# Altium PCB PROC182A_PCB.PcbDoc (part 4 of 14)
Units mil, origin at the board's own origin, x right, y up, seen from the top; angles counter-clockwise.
Board outline 3168.31 x 3700.79 mil, 8 copper layers (Top Layer, L2_GND1, L3_SIG1, L4_PWR1, L5_PWR2, L6_SIG2, L7_GND2, Bottom Layer), stack 58.1 mil thick; 580 components, 391 nets, 8314 pads, 4370 vias.
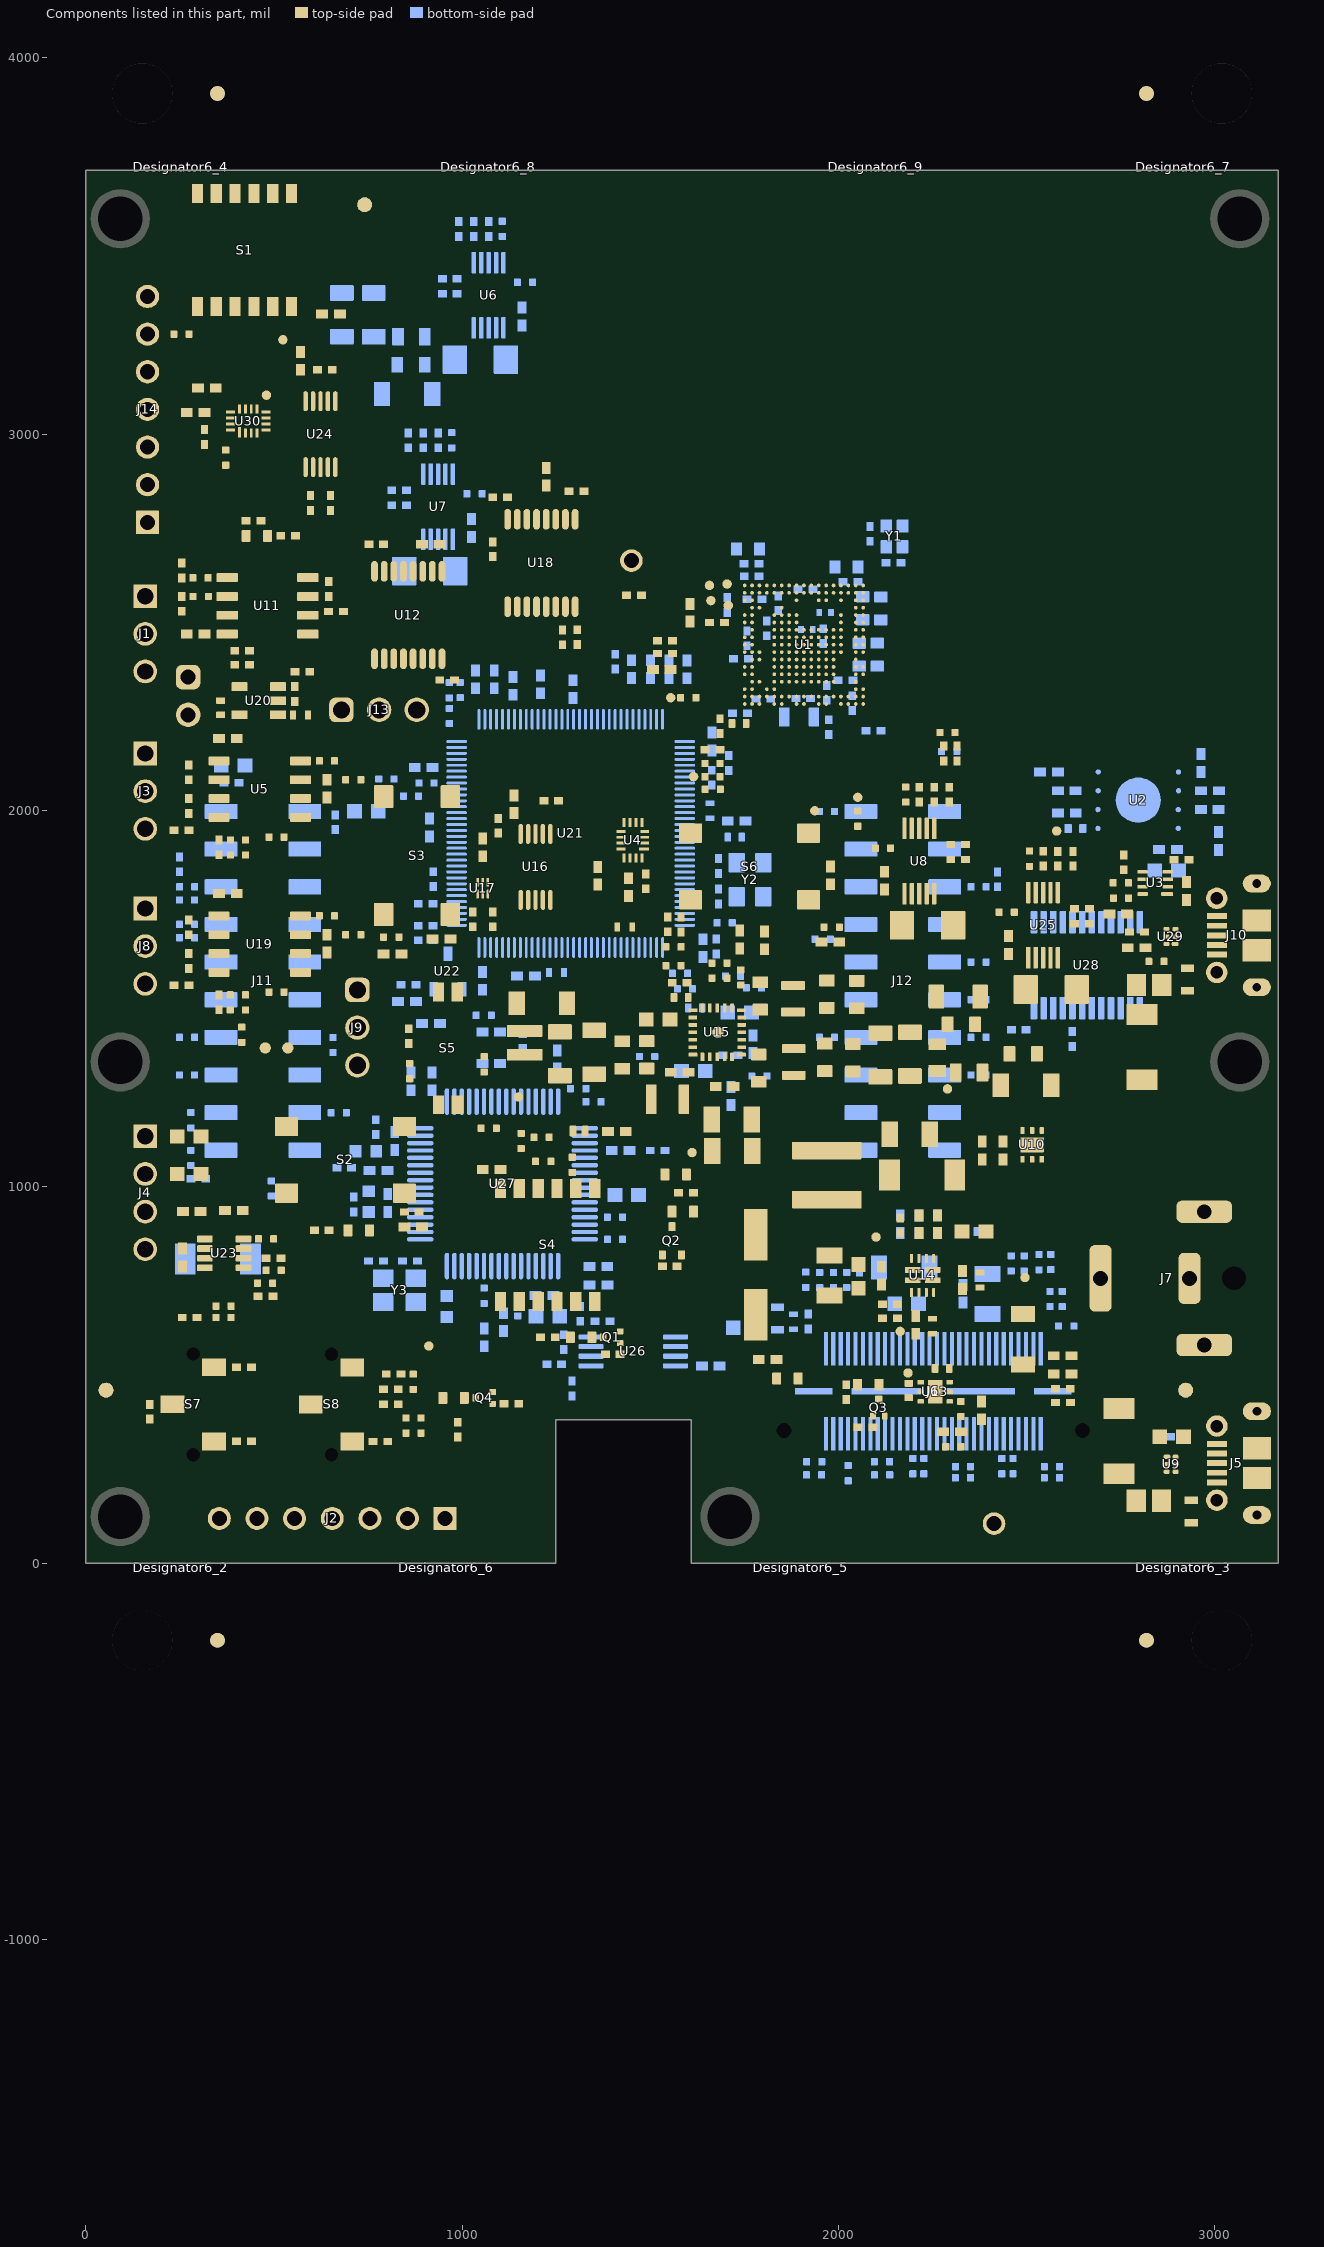
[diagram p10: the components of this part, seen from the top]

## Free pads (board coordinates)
  round 1 on Mech13: 0(1166.41,3201.26)
  round 10 on Mech16: 1(51.93,-1645.55) 1(51.93,-1645.55) 1(51.93,3654.45) 1(51.93,3654.45) 1(498.84,933.96) 1(512.82,933.96) 1(1827.42,1591.75) 1(1838.84,1591.75) 1(2281.51,930.17) 1(2297.85,930.17) 1(2467.76,1576.45) 1(2479.77,1576.45) 1(2612.3,1685.9) 1(2612.3,2360.9) 1(2622.49,1685.9) 1(2622.49,2360.9) 1(2807.83,-1645.55) 1(2807.83,-1645.55) 1(2807.83,3654.45) 1(2807.83,3654.45) 1(2808,1436.99) 1(2808,1830.69) 1(2808,2111.99) 1(2808,2505.69)
  round 7.87 on Mech16: 1(88.55,490.85) 1(89.2,516.08) 1(91.65,3514.31) 1(92.3,3539.55) 1(104.28,447.28) 1(105.05,555.83) 1(107.38,3470.75) 1(108.15,3579.3) 1(116.37,432.53) 1(119.47,3455.99) 1(121.82,574.49) 1(124.92,3597.95) 1(154.21,409.14) 1(154.21,592.82) 1(157.31,3432.61) 1(157.31,3616.29) 1(170.47,596.72) 1(173.57,3620.19) 1(179.46,404.32) 1(182.56,3427.79) 1(209.47,594.61) 1(212.56,3618.07) 1(222.4,411.76) 1(224.15,589.45) 1(225.5,3435.22) 1(227.25,3612.92) 1(239.67,421.21) 1(242.77,3444.67) 1(255.77,566.86) 1(258.87,3590.32) 1(265.38,447.28) 1(268.48,3470.75) 1(268.67,549.39) 1(271.77,3572.85) 1(274.05,463.41) 1(277.15,3486.88) 1(280.45,516.08) 1(281.52,496.15) 1(283.55,3539.55) 1(284.62,3519.61) 1(348.27,462.43) 1(348.27,501.8) 1(370.78,1047.45) 1(370.78,1047.45) 1(370.78,1061.62) 1(370.78,2033.28) 1(370.78,2047.45) 1(370.78,2047.45) 1(378.99,647.44) 1(378.99,761.62) 1(378.99,833.28) 1(378.99,947.46) 1(378.99,947.46) 1(379.54,647.45) 1(423.07,446.68) 1(423.07,501.8) 1(478.99,936.43) 1(478.99,936.43) 1(478.99,947.46) 1(478.99,947.46) 1(478.99,947.46) 1(479.54,647.45) 1(479.54,647.45) 1(479.54,661.62) 1(519.1,936.43) 1(519.1,936.43) 1(519.1,947.46) 1(519.1,947.46) 1(521.97,553.8) 1(521.97,561.67) 1(521.97,452.42) 1(521.97,472.1) 1(570.78,1047.45) 1(570.78,1047.45) 1(570.78,1061.62) 1(570.78,2033.28) 1(570.78,2047.45) 1(570.78,2047.45) 1(606.62,457.34) 1(606.62,465.21) 1(606.62,553.8) 1(606.62,561.67) 1(634.39,639.07) 1(634.39,723.72) 1(641.39,789.13) 1(641.39,873.77) 1(642.27,639.07) 1(642.27,723.72) 1(649.27,789.13) 1(649.27,873.77) 1(673.7,1905.54) 1(673.7,1905.54) 1(673.7,2035.47) 1(673.7,2035.47) 1(718.13,313.18) 1(718.13,397.83) 1(722.13,494.18) 1(722.13,578.83) 1(723.96,639.07) 1(726.01,313.18) 1(726.01,397.83) 1(730.01,494.18) 1(730.01,578.83) 1(730.85,723.72) 1(730.96,789.13) 1(737.85,873.77) 1(738.72,723.72) 1(743.64,639.07) 1(745.72,873.77) 1(750.64,789.13) 1(760.31,1905.54) 1(760.31,2035.47) 1(807.7,313.18) 1(811.7,494.18) 1(814.59,397.83) 1(818.59,578.83) 1(822.46,397.83) 1(826.46,578.83) 1(827.38,313.18) 1(831.38,494.18) 1(835.9,1474.32) 1(835.9,1494.01) 1(835.9,1494.01) 1(855.27,1151.84) 1(855.27,1194.16) 1(856.28,1905.54) 1(856.28,2035.47) 1(867.39,1494.01) 1(922.51,1494.01) 1(942.9,1905.54) 1(942.9,1905.54) 1(942.9,2035.47) 1(942.9,2035.47) 1(954.01,1474.32) 1(954.01,1494.01) 1(954.01,1494.01) 1(975.34,1111.48) 1(975.34,1194.16) 1(989.84,321.77) 1(994.76,237.13) 1(1002.64,237.13) 1(1009.53,321.77) 1(1091.22,237.13) 1(1091.22,321.77) 1(1099.09,237.13) 1(1099.09,321.77) 1(1126.49,1380.34) 1(1126.49,1396.09) 1(1126.49,1411.84) 1(1126.49,1427.58) 1(1126.49,1443.33) 1(1126.49,1459.08) 1(1126.49,1474.83) 1(1126.49,1490.58) 1(1126.49,1506.32) 1(1126.49,1522.07) 1(1126.49,1537.82) 1(1126.49,1553.57) 1(1126.49,1569.32) 1(1126.49,1585.06) 1(1126.49,1600.81) 1(1126.49,1616.56) 1(1126.49,1632.31) 1(1126.49,1648.06) 1(1126.49,1663.8) 1(1126.49,1679.55) 1(1126.49,1695.3) 1(1126.49,1711.05) 1(1126.49,1726.8) 1(1126.49,1742.54) 1(1126.49,1758.29) 1(1126.49,1774.04) 1(1126.49,1789.79) 1(1126.49,1805.54) 1(1126.49,1821.28) 1(1126.49,1837.03) 1(1126.49,1852.78) 1(1126.49,1868.53) 1(1173.74,1380.34) 1(1173.74,1396.09) 1(1173.74,1411.84) 1(1173.74,1427.58) 1(1173.74,1443.33) 1(1173.74,1459.08) 1(1173.74,1474.83) 1(1173.74,1490.58) 1(1173.74,1506.32) 1(1173.74,1522.07) 1(1173.74,1537.82) 1(1173.74,1553.57) 1(1173.74,1569.32) 1(1173.74,1585.06) 1(1173.74,1600.81) 1(1173.74,1616.56) 1(1173.74,1632.31) 1(1173.74,1648.06) 1(1173.74,1663.8) 1(1173.74,1679.55) 1(1173.74,1695.3) 1(1173.74,1711.05) 1(1173.74,1726.8) 1(1173.74,1742.54) 1(1173.74,1758.29) 1(1173.74,1774.04) 1(1173.74,1789.79) 1(1173.74,1805.54) 1(1173.74,1821.28) 1(1173.74,1837.03) 1(1173.74,1852.78) 1(1173.74,1868.53) 1(1205.23,1376.4) 1(1205.23,1376.4) 1(1205.23,1872.47) 1(1205.23,1872.47) 1(1209.17,1297.66) 1(1209.17,1344.91) 1(1209.17,1903.96) 1(1209.17,1951.21) 1(1224.92,1297.66) 1(1224.92,1344.91) 1(1224.92,1903.96) 1(1224.92,1951.21) 1(1240.66,1297.66) 1(1240.66,1344.91) 1(1240.66,1903.96) 1(1240.66,1951.21) 1(1256.41,1297.66) 1(1256.41,1344.91) 1(1256.41,1903.96) 1(1256.41,1951.21) 1(1272.16,1297.66) 1(1272.16,1344.91) 1(1272.16,1903.96) 1(1272.16,1951.21) 1(1287.91,1297.66) 1(1287.91,1344.91) 1(1287.91,1903.96) 1(1287.91,1951.21) 1(1303.66,1297.66) 1(1303.66,1344.91) 1(1303.66,1903.96) 1(1303.66,1951.21) 1(1319.4,1297.66) 1(1319.4,1344.91) 1(1319.4,1903.96) 1(1319.4,1951.21) 1(1335.15,1297.66) 1(1335.15,1344.91) 1(1335.15,1903.96) 1(1335.15,1951.21) 1(1348.35,237.58) 1(1348.35,245.46) 1(1348.35,334.04) 1(1348.35,341.91) 1(1350.9,1297.66) 1(1350.9,1344.91) 1(1350.9,1903.96) 1(1350.9,1951.21) 1(1366.65,1297.66) 1(1366.65,1344.91) 1(1366.65,1903.96) 1(1366.65,1951.21) 1(1382.4,1297.66) 1(1382.4,1344.91) 1(1382.4,1903.96) 1(1382.4,1951.21) 1(1398.14,1297.66) 1(1398.14,1344.91) 1(1398.14,1903.96) 1(1398.14,1951.21) 1(1413.89,1297.66) 1(1413.89,1344.91) 1(1413.89,1903.96) 1(1413.89,1951.21) 1(1429.64,1297.66) 1(1429.64,1344.91) 1(1429.64,1903.96) 1(1429.64,1951.21) 1(1433,327.15) 1(1433,346.84) 1(1433,237.58) 1(1433,245.46) 1(1445.39,1297.66) 1(1445.39,1344.91) 1(1445.39,1903.96) 1(1445.39,1951.21) 1(1461.14,1297.66) 1(1461.14,1344.91) 1(1461.14,1903.96) 1(1461.14,1951.21) 1(1476.89,1297.66) 1(1476.89,1344.91) 1(1476.89,1903.96) 1(1476.89,1951.21) 1(1492.63,1297.66) 1(1492.63,1344.91) 1(1492.63,1903.96) 1(1492.63,1951.21) 1(1508.38,1297.66) 1(1508.38,1344.91) 1(1508.38,1903.96) 1(1508.38,1951.21) 1(1524.13,1297.66) 1(1524.13,1344.91) 1(1524.13,1903.96) 1(1524.13,1951.21) 1(1539.88,1297.66) 1(1539.88,1344.91) 1(1539.88,1903.96) 1(1539.88,1951.21) 1(1555.63,1297.66) 1(1555.63,1344.91) 1(1555.63,1903.96) 1(1555.63,1951.21) 1(1571.37,1297.66) 1(1571.37,1344.91) 1(1571.37,1903.96) 1(1571.37,1951.21) 1(1587.12,1297.66) 1(1587.12,1344.91) 1(1587.12,1903.96) 1(1587.12,1951.21) 1(1602.87,1297.66) 1(1602.87,1344.91) 1(1602.87,1903.96) 1(1602.87,1951.21) 1(1618.62,1297.66) 1(1618.62,1344.91) 1(1618.62,1903.96) 1(1618.62,1951.21) 1(1634.37,1297.66) 1(1634.37,1344.91) 1(1634.37,1903.96) 1(1634.37,1951.21) 1(1650.11,1297.66) 1(1650.11,1344.91) 1(1650.11,1903.96) 1(1650.11,1951.21) 1(1665.86,1297.66) 1(1665.86,1344.91) 1(1665.86,1903.96) 1(1665.86,1951.21) 1(1681.61,1297.66) 1(1681.61,1344.91) 1(1681.61,1903.96) 1(1681.61,1951.21) 1(1697.36,1297.66) 1(1697.36,1344.91) 1(1697.36,1903.96) 1(1697.36,1951.21) 1(1701.29,1376.4) 1(1701.29,1376.4) 1(1701.29,1872.47) 1(1701.29,1872.47) 1(1716.69,905.12) 1(1732.58,1062.84) 1(1732.58,1062.84) 1(1732.58,1184.89) 1(1732.58,1184.89) 1(1732.79,1380.34) 1(1732.79,1396.09) 1(1732.79,1411.84) 1(1732.79,1427.58) 1(1732.79,1443.33) 1(1732.79,1459.08) 1(1732.79,1474.83) 1(1732.79,1490.58) 1(1732.79,1506.32) 1(1732.79,1522.07) 1(1732.79,1537.82) 1(1732.79,1553.57) 1(1732.79,1569.32) 1(1732.79,1585.06) 1(1732.79,1600.81) 1(1732.79,1616.56) 1(1732.79,1632.31) 1(1732.79,1648.06) 1(1732.79,1663.8) 1(1732.79,1679.55) 1(1732.79,1695.3) 1(1732.79,1711.05) 1(1732.79,1726.8) 1(1732.79,1742.54) 1(1732.79,1758.29) 1(1732.79,1774.04) 1(1732.79,1789.79) 1(1732.79,1805.54) 1(1732.79,1821.28) 1(1732.79,1837.03) 1(1732.79,1852.78) 1(1732.79,1868.53) 1(1775,-231.11) 1(1780.03,1380.34) 1(1780.03,1396.09) 1(1780.03,1411.84) 1(1780.03,1427.58) 1(1780.03,1443.33) 1(1780.03,1459.08) 1(1780.03,1474.83) 1(1780.03,1490.58) 1(1780.03,1506.32) 1(1780.03,1522.07) 1(1780.03,1537.82) 1(1780.03,1553.57) 1(1780.03,1569.32) 1(1780.03,1585.06) 1(1780.03,1600.81) 1(1780.03,1616.56) 1(1780.03,1632.31) 1(1780.03,1648.06) 1(1780.03,1663.8) 1(1780.03,1679.55) 1(1780.03,1695.3) 1(1780.03,1711.05) 1(1780.03,1726.8) 1(1780.03,1742.54) 1(1780.03,1758.29) 1(1780.03,1774.04) 1(1780.03,1789.79) 1(1780.03,1805.54) 1(1780.03,1821.28) 1(1780.03,1837.03) 1(1780.03,1852.78) 1(1780.03,1868.53) 1(1785.59,1027.17) 1(1815.12,278.25) 1(1815.12,278.25) 1(1815.12,306.79) 1(1815.12,481) 1(1815.12,490.84) 1(1815.12,490.84) 1(1824.96,490.84) 1(1843.67,278.25) 1(1843.89,-109.06) 1(1856.45,905.12) 1(1856.45,1027.17) 1(1858.57,1062.84) 1(1858.57,1062.84) 1(1858.57,1184.89) 1(1858.57,1184.89) 1(1872.3,1806) 1(1872.3,1806) 1(1872.3,1883.5) 1(1872.3,1883.5) 1(1872.3,1903.5) 1(1872.3,1903.5) 1(1872.3,1983.5) 1(1872.3,1983.5) 1(1872.3,2003.5) 1(1872.3,2003.5) 1(1872.3,2081) 1(1872.3,2081) 1(1881.8,1793.5) 1(1881.8,1793.5) 1(1881.8,2093.5) 1(1881.8,2093.5) 1(1882.3,1893.5) 1(1882.3,1893.5) 1(1882.3,1993.5) 1(1882.3,1993.5) 1(1885.3,1793.5) 1(1885.3,2093.5) 1(1885.3,2093.5) 1(1914.76,-231.11) 1(1914.76,-109.06) 1(1957.3,1793.5) 1(1957.3,2093.5) 1(1957.3,2093.5) 1(1960.3,1893.5) 1(1960.3,1893.5) 1(1960.3,1993.5) 1(1960.3,1993.5) 1(1960.8,1793.5) 1(1960.8,1793.5) 1(1960.8,2093.5) 1(1960.8,2093.5) 1(1970.3,1806) 1(1970.3,1806) 1(1970.3,1883.5) 1(1970.3,1883.5) 1(1970.3,1903.5) 1(1970.3,1903.5) 1(1970.3,1983.5) 1(1970.3,1983.5) 1(1970.3,2003.5) 1(1970.3,2003.5) 1(1970.3,2081) 1(1970.3,2081) 1(1998.19,278.25) 1(1998.19,490.84) 1(2008.04,278.25) 1(2008.04,278.25) 1(2008.04,288.09) 1(2008.04,481) 1(2008.04,490.84) 1(2008.04,490.84) 1(2070.78,1047.45) 1(2070.78,1047.45) 1(2070.78,1061.62) 1(2070.78,2033.28) 1(2070.78,2047.45) 1(2070.78,2047.45) 1(2161.47,647.44) 1(2161.47,761.62) 1(2161.47,833.28) 1(2161.47,947.46) 1(2161.47,947.46) 1(2162.02,647.45) 1(2246.76,317.85) 1(2246.76,325.73) 1(2246.76,216.48) 1(2246.76,236.16) 1(2261.47,936.43) 1(2261.47,936.43) 1(2261.47,947.46) 1(2261.47,947.46) 1(2261.47,947.46) 1(2262.02,647.45) 1(2262.02,647.45) 1(2262.02,661.62) 1(2270.78,1047.45) 1(2270.78,1047.45) 1(2270.78,1061.62) 1(2270.78,2033.28) 1(2270.78,2047.45) 1(2270.78,2047.45) 1(2301.58,936.43) 1(2301.58,936.43) 1(2301.58,947.46) 1(2301.58,947.46) 1(2303.86,-14.52) 1(2303.86,107.53) 1(2309.97,-1229.15) 1(2309.97,-1229.15) 1(2309.97,-1142.54) 1(2309.97,-1046.57) 1(2309.97,-959.95) 1(2309.97,-959.95) 1(2320.65,3534.31) 1(2321.3,3559.55) 1(2328.55,490.85) 1(2329.2,516.08) 1(2331.41,221.4) 1(2331.41,229.27) 1(2331.41,317.85) 1(2331.41,325.73) 1(2336.38,3490.75) 1(2337.15,3599.3) 1(2344.28,447.28) 1(2345.05,555.83) 1(2348.47,3475.99) 1(2353.92,3617.95) 1(2356.37,432.53) 1(2361.82,574.49) 1(2374.73,-14.52) 1(2385.3,1191) 1(2385.3,1191) 1(2385.3,1268.5) 1(2385.3,1268.5) 1(2385.3,1288.5) 1(2385.3,1288.5) 1(2385.3,1368.5) 1(2385.3,1368.5) 1(2385.3,1388.5) 1(2385.3,1388.5) 1(2385.3,1466) 1(2385.3,1466) 1(2386.31,3452.61) 1(2386.31,3636.29) 1(2394.21,409.14) 1(2394.21,592.82) 1(2394.8,1178.5) 1(2394.8,1178.5) 1(2394.8,1478.5) 1(2394.8,1478.5) 1(2395.3,1278.5) 1(2395.3,1278.5) 1(2395.3,1378.5) 1(2395.3,1378.5) 1(2398.3,1178.5) 1(2398.3,1178.5) 1(2398.3,1478.5) 1(2402.57,3640.19) 1(2410.47,596.72) 1(2411.56,3447.79) 1(2419.46,404.32) 1(2439.89,-1229.15) 1(2439.89,-1229.15) 1(2439.89,-1142.54) 1(2439.89,-1046.57) 1(2439.89,-959.95) 1(2439.89,-959.95) 1(2441.56,3638.07) 1(2443.63,107.53) 1(2449.47,594.61) 1(2454.5,3455.22) 1(2456.25,3632.92) 1(2462.4,411.76) 1(2464.15,589.45) 1(2470.3,1178.5) 1(2470.3,1178.5) 1(2470.3,1478.5) 1(2471.77,3464.67) 1(2473.3,1278.5) 1(2473.3,1278.5) 1(2473.3,1378.5) 1(2473.3,1378.5) 1(2473.8,1178.5) 1(2473.8,1178.5) 1(2473.8,1478.5) 1(2473.8,1478.5) 1(2474.24,1604.98) 1(2479.67,421.21) 1(2483.3,1191) 1(2483.3,1191) 1(2483.3,1268.5) 1(2483.3,1268.5) 1(2483.3,1288.5) 1(2483.3,1288.5) 1(2483.3,1368.5) 1(2483.3,1368.5) 1(2483.3,1388.5) 1(2483.3,1388.5) 1(2483.3,1466) 1(2483.3,1466) 1(2486.05,1671.91) 1(2487.87,3610.32) 1(2495.77,566.86) 1(2497.48,3490.75) 1(2500.77,3592.85) 1(2501.8,1604.98) 1(2501.8,1671.91) 1(2505.38,447.28) 1(2506.15,3506.88) 1(2508.67,549.39) 1(2512.55,3559.55) 1(2513.62,3539.61) 1(2514.05,463.41) 1(2520.45,516.08) 1(2521.52,496.15)
  round 7 on Mech16: 1(146.93,-380.05) 1(146.93,-380.05) 1(146.93,-339.05) 1(146.93,-339.05) 1(147.5,-330.06) 1(147.5,-330.06) 1(147.5,-289.06) 1(147.5,-289.06) 1(147.5,-231.63) 1(147.5,-231.63) 1(147.5,-190.63) 1(147.5,-190.63) 1(147.55,-281.52) 1(147.55,-281.52) 1(147.55,-240.52) 1(147.55,-240.52) 1(148.55,-432.52) 1(148.55,-432.52) 1(148.55,-391.52) 1(148.55,-391.52) 1(163.93,1511.95) 1(163.93,1511.95) 1(163.93,1552.95) 1(163.93,1552.95) 1(163.93,1560.95) 1(163.93,1560.95) 1(163.93,1601.95) 1(163.93,1601.95) 1(163.93,1462.95) 1(163.93,1462.95) 1(163.93,1503.95) 1(163.93,1503.95) 1(169.93,-380.05) 1(169.93,-339.05) 1(170.5,-330.06) 1(170.5,-289.06) 1(170.5,-231.63) 1(170.5,-190.63) 1(170.55,-281.52) 1(170.55,-240.52) 1(171.55,-432.52) 1(171.55,-391.52) 1(186.93,1511.95) 1(186.93,1552.95) 1(186.93,1560.95) 1(186.93,1601.95) 1(186.93,1462.95) 1(186.93,1503.95) 1(219.93,-380.05) 1(219.93,-339.05) 1(220.5,-330.06) 1(220.5,-289.06) 1(220.5,-231.63) 1(220.5,-190.63) 1(220.55,-281.52) 1(220.55,-240.52) 1(221.55,-432.52) 1(221.55,-391.52) 1(236.93,1511.95) 1(236.93,1552.95) 1(236.93,1560.95) 1(236.93,1601.95) 1(236.93,1462.95) 1(236.93,1503.95) 1(242.93,-380.05) 1(242.93,-380.05) 1(242.93,-339.05) 1(242.93,-339.05) 1(243.5,-330.06) 1(243.5,-330.06) 1(243.5,-289.06) 1(243.5,-289.06) 1(243.5,-231.63) 1(243.5,-231.63) 1(243.5,-190.63) 1(243.5,-190.63) 1(243.55,-281.52) 1(243.55,-281.52) 1(243.55,-240.52) 1(243.55,-240.52) 1(244.55,-432.52) 1(244.55,-432.52) 1(244.55,-391.52) 1(244.55,-391.52) 1(259.93,1511.95) 1(259.93,1511.95) 1(259.93,1552.95) 1(259.93,1552.95) 1(259.93,1560.95) 1(259.93,1560.95) 1(259.93,1601.95) 1(259.93,1601.95) 1(259.93,1462.95) 1(259.93,1462.95) 1(259.93,1503.95) 1(259.93,1503.95) 1(365.55,-403.52) 1(365.55,-403.52) 1(365.55,-362.52) 1(365.55,-362.52) 1(366.55,-76.52) 1(366.55,-76.52) 1(366.55,-35.52) 1(366.55,-35.52) 1(366.55,-25.52) 1(366.55,-25.52) 1(366.55,15.48) 1(366.55,15.48) 1(367.05,-353.02) 1(367.05,-353.02) 1(367.05,-330.02) 1(367.05,-280.02) 1(367.05,-257.02) 1(367.05,-257.02) 1(367.55,76.48) 1(367.55,76.48) 1(367.55,117.48) 1(367.55,117.48) 1(367.8,25.48) 1(367.8,25.48) 1(367.8,66.48) 1(367.8,66.48) 1(368.55,127.48) 1(368.55,127.48) 1(368.55,168.48) 1(368.55,168.48) 1(388.55,-403.52) 1(388.55,-362.52) 1(389.55,-76.52) 1(389.55,-35.52) 1(389.55,-25.52) 1(389.55,15.48) 1(390.55,76.48) 1(390.55,117.48) 1(390.8,25.48) 1(390.8,66.48) 1(391.55,127.48) 1(391.55,168.48) 1(408.05,-353.02) 1(408.05,-353.02) 1(408.05,-330.02) 1(408.05,-280.02) 1(408.05,-257.02) 1(408.05,-257.02) 1(418.05,-353.02) 1(418.05,-353.02) 1(418.05,-330.02) 1(418.05,-280.02) 1(418.05,-257.02) 1(418.05,-257.02) 1(438.55,-403.52) 1(438.55,-362.52) 1(439.55,-76.52) 1(439.55,-35.52) 1(439.55,-25.52) 1(439.55,15.48) 1(440.55,76.48) 1(440.55,117.48) 1(440.8,25.48) 1(440.8,66.48) 1(441.55,127.48) 1(441.55,168.48) 1(459.05,-353.02) 1(459.05,-353.02) 1(459.05,-330.02) 1(459.05,-280.02) 1(459.05,-257.02) 1(459.05,-257.02) 1(461.55,-403.52) 1(461.55,-403.52) 1(461.55,-362.52) 1(461.55,-362.52) 1(462.55,-76.52) 1(462.55,-76.52) 1(462.55,-35.52) 1(462.55,-35.52) 1(462.55,-25.52) 1(462.55,-25.52) 1(462.55,15.48) 1(462.55,15.48) 1(463.55,76.48) 1(463.55,76.48) 1(463.55,117.48) 1(463.55,117.48) 1(463.8,25.48) 1(463.8,25.48) 1(463.8,66.48) 1(463.8,66.48) 1(464.55,127.48) 1(464.55,127.48) 1(464.55,168.48) 1(464.55,168.48) 1(523.66,8.02) 1(523.66,8.02) 1(523.66,43.45) 1(523.66,161.56) 1(523.66,196.99) 1(523.66,196.99) 1(561.06,2784.02) 1(561.06,2784.02) 1(561.06,2819.45) 1(561.06,2937.56) 1(561.06,2972.99) 1(561.06,2972.99) 1(568.63,-761.82) 1(568.63,-761.82) 1(568.63,-720.82) 1(568.63,-720.82) 1(568.63,-685.96) 1(568.63,-685.96) 1(568.63,-644.96) 1(568.63,-644.96) 1(568.81,-504.13) 1(568.81,-504.13) 1(568.81,-408.86) 1(568.81,-408.86) 1(570.8,208.5) 1(570.8,208.5) 1(570.8,231.5) 1(570.8,281.5) 1(570.8,304.5) 1(570.8,304.5) 1(591.63,-761.82) 1(591.63,-720.82) 1(591.63,-685.96) 1(591.63,-644.96) 1(593.66,-636.53) 1(593.66,-636.53) 1(593.66,-610.55) 1(593.66,-542.55) 1(593.66,-516.57) 1(593.66,-516.57) 1(598.43,-920.55) 1(598.43,-920.55) 1(598.43,-897.55) 1(598.43,-847.55) 1(598.43,-824.55) 1(598.43,-824.55) 1(604.24,-504.13) 1(604.24,-408.86) 1(611.8,208.5) 1(611.8,208.5) 1(611.8,231.5) 1(611.8,281.5) 1(611.8,304.5) 1(611.8,304.5) 1(618.93,8.02) 1(618.93,8.02) 1(618.93,43.45) 1(618.93,161.56) 1(618.93,196.99) 1(618.93,196.99) 1(639.43,-920.55) 1(639.43,-920.55) 1(639.43,-897.55) 1(639.43,-847.55) 1(639.43,-824.55) 1(639.43,-824.55) 1(641.63,-761.82) 1(641.63,-720.82) 1(641.63,-685.96) 1(641.63,-644.96) 1(648.13,-636.53) 1(648.13,-636.53) 1(648.13,-610.55) 1(648.13,-542.55) 1(648.13,-516.57) 1(648.13,-516.57) 1(648.43,-920.55) 1(648.43,-920.55) 1(648.43,-897.55) 1(648.43,-847.55) 1(648.43,-824.55) 1(648.43,-824.55) 1(656.34,2784.02) 1(656.34,2784.02) 1(656.34,2819.45) 1(656.34,2937.56) 1(656.34,2972.99) 1(656.34,2972.99) 1(664.63,-761.82) 1(664.63,-761.82) 1(664.63,-720.82) 1(664.63,-720.82) 1(664.63,-685.96) 1(664.63,-685.96) 1(664.63,-644.96) 1(664.63,-644.96) 1(689.43,-920.55) 1(689.43,-920.55) 1(689.43,-897.55) 1(689.43,-847.55) 1(689.43,-824.55) 1(689.43,-824.55) 1(694.55,-569.52) 1(694.55,-569.52) 1(694.55,-528.52) 1(694.55,-528.52) 1(698.3,-755.05) 1(698.3,-755.05) 1(698.3,-714.05) 1(698.3,-714.05) 1(699.62,-921.9) 1(699.62,-921.9) 1(699.62,-898.9) 1(699.62,-848.9) 1(699.62,-825.9) 1(699.62,-825.9) 1(703.3,-665.05) 1(703.3,-665.05) 1(703.3,-624.05) 1(703.3,-624.05) 1(717.55,-569.52) 1(717.55,-528.52) 1(721.3,-755.05) 1(721.3,-714.05) 1(722.35,-504.13) 1(722.35,-408.86) 1(726.3,-665.05) 1(726.3,-624.05) 1(740.62,-921.9) 1(740.62,-921.9) 1(740.62,-898.9) 1(740.62,-848.9) 1(740.62,-825.9) 1(740.62,-825.9) 1(741.92,149) 1(741.92,149) 1(741.92,190) 1(741.92,190) 1(751.3,-141) 1(751.3,-141) 1(751.3,-100) 1(751.3,-100) 1(752.3,33) 1(752.3,33) 1(752.3,74) 1(752.3,74) 1(752.67,-58) 1(752.67,-58) 1(752.67,-17) 1(752.67,-17) 1(754.62,-921.9) 1(754.62,-921.9) 1(754.62,-898.9) 1(754.62,-848.9) 1(754.62,-825.9) 1(754.62,-825.9) 1(757.79,-504.13) 1(757.79,-504.13) 1(757.79,-408.86) 1(757.79,-408.86) 1(764.92,149) 1(764.92,190) 1(767.55,-569.52) 1(767.55,-528.52) 1(771.3,-755.05) 1(771.3,-714.05) 1(774.3,-141) 1(774.3,-100) 1(775.3,33) 1(775.3,74) 1(775.66,1576.02) 1(775.66,1576.02) 1(775.66,1611.45) 1(775.66,1729.56) 1(775.66,1764.99) 1(775.66,1764.99) 1(775.67,-58) 1(775.67,-17) 1(776.3,-665.05) 1(776.3,-624.05) 1(787.56,857.95) 1(787.56,857.95) 1(787.56,898.95) 1(787.56,898.95) 1(790.55,-569.52) 1(790.55,-569.52) 1(790.55,-528.52) 1(790.55,-528.52) 1(793.93,2757.3) 1(793.93,2757.3) 1(793.93,2798.3) 1(793.93,2798.3) 1(793.93,2807.3) 1(793.93,2807.3) 1(793.93,2848.3) 1(793.93,2848.3) 1(793.93,2907.3) 1(793.93,2907.3) 1(793.93,2948.3) 1(793.93,2948.3) 1(793.93,2857.3) 1(793.93,2857.3) 1(793.93,2898.3) 1(793.93,2898.3) 1(794.3,-755.05) 1(794.3,-755.05) 1(794.3,-714.05) 1(794.3,-714.05) 1(795.62,-921.9) 1(795.62,-921.9) 1(795.62,-898.9) 1(795.62,-848.9) 1(795.62,-825.9) 1(795.62,-825.9) 1(799.3,-665.05) 1(799.3,-665.05) 1(799.3,-624.05) 1(799.3,-624.05) 1(810.56,857.95) 1(810.56,898.95) 1(812.19,733.89) 1(812.19,733.89) 1(812.19,774.89) 1(812.19,774.89) 1(814.92,149) 1(814.92,190) 1(816.93,2757.3) 1(816.93,2798.3) 1(816.93,2807.3) 1(816.93,2848.3) 1(816.93,2907.3) 1(816.93,2948.3) 1(816.93,2857.3) 1(816.93,2898.3) 1(820.8,-924.5) 1(820.8,-924.5) 1(820.8,-901.5) 1(820.8,-851.5) 1(820.8,-828.5) 1(820.8,-828.5) 1(824.3,-141) 1(824.3,-100) 1(825.3,33) 1(825.3,74) 1(825.67,-58) 1(825.67,-17) 1(835.19,733.89) 1(835.19,774.89) 1(837.92,149) 1(837.92,149) 1(837.92,190) 1(837.92,190) 1(838.53,1286.05) 1(838.53,1359.05) 1(838.53,1359.05) 1(838.53,1263.05) 1(838.53,1263.05) 1(838.53,1336.05) 1(847.3,-141) 1(847.3,-141) 1(847.3,-100) 1(847.3,-100) 1(848.3,33) 1(848.3,33) 1(848.3,74) 1(848.3,74) 1(848.67,-58) 1(848.67,-58) 1(848.67,-17) 1(848.67,-17) 1(851.43,981.45) 1(851.43,981.45) 1(851.43,1004.45) 1(851.43,1054.45) 1(851.43,1077.45) 1(851.43,1077.45) 1(853.67,224) 1(853.67,224) 1(853.67,265) 1(853.67,265) 1(860.56,857.95) 1(860.56,898.95) 1(861.8,-924.5) 1(861.8,-924.5) 1(861.8,-901.5) 1(861.8,-851.5) 1(861.8,-828.5) 1(861.8,-828.5) 1(866.93,2757.3) 1(866.93,2798.3) 1(866.93,2807.3) 1(866.93,2848.3) 1(866.93,2907.3) 1(866.93,2948.3) 1(866.93,2857.3) 1(866.93,2898.3) 1(870.93,1576.02) 1(870.93,1576.02) 1(870.93,1611.45) 1(870.93,1729.56) 1(870.93,1764.99) 1(870.93,1764.99) 1(876.67,224) 1(876.67,265) 1(879.53,1263.05) 1(879.53,1263.05) 1(879.53,1336.05) 1(879.53,1286.05) 1(879.53,1359.05) 1(879.53,1359.05) 1(880.8,-924.5) 1(880.8,-924.5) 1(880.8,-901.5) 1(880.8,-851.5) 1(880.8,-828.5) 1(880.8,-828.5) 1(883.56,857.95) 1(883.56,857.95) 1(883.56,898.95) 1(883.56,898.95) 1(885.19,733.89) 1(885.19,774.89) 1(887.53,1263.25) 1(887.53,1263.25) 1(887.53,1286.25) 1(887.53,1336.25) 1(887.53,1359.25) 1(887.53,1359.25) 1(889.93,2757.3) 1(889.93,2757.3) 1(889.93,2798.3) 1(889.93,2798.3) 1(889.93,2807.3) 1(889.93,2807.3) 1(889.93,2848.3) 1(889.93,2848.3) 1(889.93,2907.3) 1(889.93,2907.3) 1(889.93,2948.3) 1(889.93,2948.3) 1(889.93,2857.3) 1(889.93,2857.3) 1(889.93,2898.3) 1(889.93,2898.3) 1(892.43,981.45) 1(892.43,981.45) 1(892.43,1004.45) 1(892.43,1054.45) 1(892.43,1077.45) 1(892.43,1077.45) 1(908.19,733.89) 1(908.19,733.89) 1(908.19,774.89) 1(908.19,774.89) 1(917.3,172) 1(917.3,172) 1(917.3,213) 1(917.3,213) 1(921.8,-924.5) 1(921.8,-924.5) 1(921.8,-901.5) 1(921.8,-851.5) 1(921.8,-828.5) 1(921.8,-828.5) 1(925.03,961.26) 1(925.03,961.26) 1(925.03,987.25) 1(925.03,1055.25) 1(925.03,1081.23) 1(925.03,1081.23) 1(926.67,224) 1(926.67,265) 1(928.53,1263.25) 1(928.53,1263.25) 1(928.53,1286.25) 1(928.53,1336.25) 1(928.53,1359.25) 1(928.53,1359.25) 1(937.1,1259.47) 1(937.1,1259.47) 1(937.1,1285.45) 1(937.1,1353.45) 1(937.1,1379.43) 1(937.1,1379.43) 1(940.3,172) 1(940.3,213) 1(949.67,224) 1(949.67,224) 1(949.67,265) 1(949.67,265) 1(979.5,961.26) 1(979.5,961.26) 1(979.5,987.25) 1(979.5,1055.25) 1(979.5,1081.23) 1(979.5,1081.23) 1(980.3,1733.01) 1(980.3,1733.01) 1(980.3,1774.01) 1(980.3,1774.01) 1(980.78,1633.1) 1(980.78,1633.1) 1(980.78,1674.1) 1(980.78,1674.1) 1(980.8,-920.87) 1(980.8,-920.87) 1(980.8,-897.87) 1(980.8,-847.87) 1(980.8,-824.87) 1(980.8,-824.87) 1(981.3,1683) 1(981.3,1683) 1(981.3,1724) 1(981.3,1724) 1(990.3,172) 1(990.3,213) 1(991.56,1259.47) 1(991.56,1259.47) 1(991.56,1285.45) 1(991.56,1353.45) 1(991.56,1379.43) 1(991.56,1379.43) 1(1003.3,1733.01) 1(1003.3,1774.01) 1(1003.78,1633.1) 1(1003.78,1674.1) 1(1004.3,1683) 1(1004.3,1724) 1(1013.3,172) 1(1013.3,172) 1(1013.3,213) 1(1013.3,213) 1(1017.03,-5.48) 1(1017.03,-5.48) 1(1017.03,20.5) 1(1017.03,88.5) 1(1017.03,114.49) 1(1017.03,114.49) 1(1021.8,-920.87) 1(1021.8,-920.87) 1(1021.8,-897.87) 1(1021.8,-847.87) 1(1021.8,-824.87) 1(1021.8,-824.87) 1(1035.8,-920.87) 1(1035.8,-920.87) 1(1035.8,-897.87) 1(1035.8,-847.87) 1(1035.8,-824.87) 1(1035.8,-824.87) 1(1053.3,1733.01) 1(1053.3,1774.01) 1(1053.78,1633.1) 1(1053.78,1674.1) 1(1054.3,1683) 1(1054.3,1724) 1(1071.5,-5.48) 1(1071.5,-5.48) 1(1071.5,20.5) 1(1071.5,88.5) 1(1071.5,114.49) 1(1071.5,114.49) 1(1072.3,1957) 1(1072.3,1957) 1(1072.3,1998) 1(1072.3,1998) 1(1072.3,2007) 1(1072.3,2007) 1(1072.3,2048) 1(1072.3,2048) 1(1076.3,1733.01) 1(1076.3,1733.01) 1(1076.3,1774.01) 1(1076.3,1774.01) 1(1076.78,1633.1) 1(1076.78,1633.1) 1(1076.78,1674.1) 1(1076.78,1674.1) 1(1076.8,-920.87) 1(1076.8,-920.87) 1(1076.8,-897.87) 1(1076.8,-847.87) 1(1076.8,-824.87) 1(1076.8,-824.87) 1(1077.3,1683) 1(1077.3,1683) 1(1077.3,1724) 1(1077.3,1724) 1(1088.58,-921.9) 1(1088.58,-921.9) 1(1088.58,-898.9) 1(1088.58,-848.9) 1(1088.58,-825.9) 1(1088.58,-825.9) 1(1095.3,1957) 1(1095.3,1998) 1(1095.3,2007) 1(1095.3,2048) 1(1099.07,93.16) 1(1099.07,93.16) 1(1099.07,147.63) 1(1099.07,147.63) 1(1125.05,93.16) 1(1125.05,147.63) 1(1129.58,-921.9) 1(1129.58,-921.9) 1(1129.58,-898.9) 1(1129.58,-848.9) 1(1129.58,-825.9) 1(1129.58,-825.9) 1(1145.3,1957) 1(1145.3,1998) 1(1145.3,2007) 1(1145.3,2048) 1(1149.3,-774) 1(1149.3,-774) 1(1149.3,-733) 1(1149.3,-733) 1(1168.3,1957) 1(1168.3,1957) 1(1168.3,1998) 1(1168.3,1998) 1(1168.3,2007) 1(1168.3,2007) 1(1168.3,2048) 1(1168.3,2048) 1(1170.3,-929.2) 1(1170.3,-929.2) 1(1170.3,-888.2) 1(1170.3,-888.2) 1(1170.3,-879) 1(1170.3,-879) 1(1170.3,-838) 1(1170.3,-838) 1(1172.3,-774) 1(1172.3,-733) 1(1188.67,1103.01) 1(1188.67,1103.01) 1(1188.67,1144.01) 1(1188.67,1144.01) 1(1193.05,93.16) 1(1193.05,147.63) 1(1193.3,-929.2) 1(1193.3,-888.2) 1(1193.3,-879) 1(1193.3,-838) 1(1205.67,301) 1(1205.67,301) 1(1205.67,342) 1(1205.67,342) 1(1211.67,1103.01) 1(1211.67,1144.01) 1(1219.04,93.16) 1(1219.04,93.16) 1(1219.04,147.63) 1(1219.04,147.63) 1(1222.3,-774) 1(1222.3,-733) 1(1228.67,301) 1(1228.67,342) 1(1241.91,1998.84) 1(1241.91,1998.84) 1(1241.91,2021.84) 1(1241.91,2071.84) 1(1241.91,2094.84) 1(1241.91,2094.84) 1(1243.3,-929.2) 1(1243.3,-888.2) 1(1243.3,-879) 1(1243.3,-838) 1(1245.3,-774) 1(1245.3,-774) 1(1245.3,-733) 1(1245.3,-733) 1(1251.43,927.83) 1(1251.43,927.83) 1(1251.43,950.83) 1(1251.43,1000.83) 1(1251.43,1023.83) 1(1251.43,1023.83) 1(1261.67,1103.01) 1(1261.67,1144.01) 1(1266.3,-929.2) 1(1266.3,-929.2) 1(1266.3,-888.2) 1(1266.3,-888.2) 1(1266.3,-879) 1(1266.3,-879) 1(1266.3,-838) 1(1266.3,-838) 1(1270.74,-122.27) 1(1270.74,-122.27) 1(1270.74,-81.27) 1(1270.74,-81.27) 1(1278.24,-69.77) 1(1278.24,-69.77) 1(1278.24,-46.77) 1(1278.24,3.23) 1(1278.24,26.23) 1(1278.24,26.23) 1(1278.67,301) 1(1278.67,342) 1(1282.91,1998.84) 1(1282.91,1998.84) 1(1282.91,2021.84) 1(1282.91,2071.84) 1(1282.91,2094.84) 1(1282.91,2094.84) 1(1284.67,1103.01) 1(1284.67,1103.01) 1(1284.67,1144.01) 1(1284.67,1144.01) 1(1285.3,388) 1(1285.3,388) 1(1285.3,429) 1(1285.3,429) 1(1292.43,927.83) 1(1292.43,927.83) 1(1292.43,950.83) 1(1292.43,1000.83) 1(1292.43,1023.83) 1(1292.43,1023.83) 1(1293.74,-122.27) 1(1293.74,-81.27) 1(1301.67,301) 1(1301.67,301) 1(1301.67,342) 1(1301.67,342) 1(1306.94,957.64) 1(1306.94,957.64) 1(1306.94,980.64) 1(1306.94,1030.64) 1(1306.94,1053.64) 1(1306.94,1053.64) 1(1306.94,1062.64) 1(1306.94,1062.64) 1(1306.94,1085.64) 1(1306.94,1135.64) 1(1306.94,1158.64) 1(1306.94,1158.64) 1(1308.3,388) 1(1308.3,429) 1(1308.92,-929.2) 1(1308.92,-929.2) 1(1308.92,-888.2) 1(1308.92,-888.2) 1(1314.3,752) 1(1314.3,752) 1(1314.3,793) 1(1314.3,793) 1(1319.24,-69.77) 1(1319.24,-69.77) 1(1319.24,-46.77) 1(1319.24,3.23) 1(1319.24,26.23) 1(1319.24,26.23) 1(1331.92,-929.2) 1(1331.92,-888.2) 1(1333.24,-69.77) 1(1333.24,-69.77) 1(1333.24,-46.77) 1(1333.24,3.23) 1(1333.24,26.23) 1(1333.24,26.23) 1(1337.3,752) 1(1337.3,793) 1(1343.74,-122.27) 1(1343.74,-81.27) 1(1347.71,-882) 1(1347.71,-882) 1(1347.71,-841) 1(1347.71,-841) 1(1347.94,957.64) 1(1347.94,957.64) 1(1347.94,980.64) 1(1347.94,1030.64) 1(1347.94,1053.64) 1(1347.94,1053.64) 1(1347.94,1062.64) 1(1347.94,1062.64) 1(1347.94,1085.64) 1(1347.94,1135.64) 1(1347.94,1158.64) 1(1347.94,1158.64) 1(1358.3,388) 1(1358.3,429) 1(1363.93,553.95) 1(1363.93,553.95) 1(1363.93,594.95) 1(1363.93,594.95) 1(1363.93,618.95) 1(1363.93,618.95) 1(1363.93,659.95) 1(1363.93,659.95) 1(1366.74,-122.27) 1(1366.74,-122.27) 1(1366.74,-81.27) 1(1366.74,-81.27) 1(1370.71,-882) 1(1370.71,-841) 1(1371.28,1976.03) 1(1371.28,1976.03) 1(1371.28,1999.03) 1(1371.28,2049.03) 1(1371.28,2072.03) 1(1371.28,2072.03) 1(1374.24,-69.77) 1(1374.24,-69.77) 1(1374.24,-46.77) 1(1374.24,3.23) 1(1374.24,26.23) 1(1374.24,26.23) 1(1381.3,388) 1(1381.3,388) 1(1381.3,429) 1(1381.3,429) 1(1381.92,-929.2) 1(1381.92,-888.2) 1(1386.93,553.95) 1(1386.93,594.95) 1(1386.93,618.95) 1(1386.93,659.95) 1(1387.3,752) 1(1387.3,793) 1(1404.92,-929.2) 1(1404.92,-929.2) 1(1404.92,-888.2) 1(1404.92,-888.2) 1(1410.3,752) 1(1410.3,752) 1(1410.3,793) 1(1410.3,793) 1(1412.28,1976.03) 1(1412.28,1976.03) 1(1412.28,1999.03) 1(1412.28,2049.03) 1(1412.28,2072.03) 1(1412.28,2072.03) 1(1420.71,-882) 1(1420.71,-841) 1(1422.89,-931.23) 1(1422.89,-931.23) 1(1422.89,-890.23) 1(1422.89,-890.23) 1(1431.43,957.64) 1(1431.43,957.64) 1(1431.43,980.64) 1(1431.43,1030.64) 1(1431.43,1053.64) 1(1431.43,1053.64) 1(1431.7,1062.64) 1(1431.7,1062.64) 1(1431.7,1085.64) 1(1431.7,1135.64) 1(1431.7,1158.64) 1(1431.7,1158.64) 1(1436.93,553.95) 1(1436.93,594.95) 1(1436.93,618.95) 1(1436.93,659.95) 1(1443.71,-882) 1(1443.71,-882) 1(1443.71,-841) 1(1443.71,-841) 1(1445.89,-931.23) 1(1445.89,-890.23) 1(1452.8,1166.5) 1(1452.8,1166.5) 1(1452.8,1189.5) 1(1452.8,1239.5) 1(1452.8,1262.5) 1(1452.8,1262.5) 1(1453.93,390.95) 1(1453.93,390.95) 1(1453.93,431.95) 1(1453.93,431.95) 1(1459.52,464.19) 1(1459.52,464.19) 1(1459.52,505.19) 1(1459.52,505.19) 1(1459.93,553.95) 1(1459.93,553.95) 1(1459.93,594.95) 1(1459.93,594.95) 1(1459.93,618.95) 1(1459.93,618.95) 1(1459.93,659.95) 1(1459.93,659.95) 1(1461.19,-164.92) 1(1461.19,-164.92) 1(1461.19,-123.92) 1(1461.19,-123.92) 1(1462.09,-66.77) 1(1462.09,-66.77) 1(1462.09,-25.77) 1(1462.09,-25.77) 1(1462.09,-16.77) 1(1462.09,-16.77) 1(1462.09,24.23) 1(1462.09,24.23) 1(1462.09,-116.78) 1(1462.09,-116.78) 1(1462.09,-75.78) 1(1462.09,-75.78) 1(1462.09,33.22) 1(1462.09,33.22) 1(1462.09,74.22) 1(1462.09,74.22) 1(1472.43,957.64) 1(1472.43,957.64) 1(1472.43,980.64) 1(1472.43,1030.64) 1(1472.43,1053.64) 1(1472.43,1053.64) 1(1472.7,1062.64) 1(1472.7,1062.64) 1(1472.7,1085.64) 1(1472.7,1135.64) 1(1472.7,1158.64) 1(1472.7,1158.64) 1(1476.93,390.95) 1(1476.93,431.95) 1(1482.52,464.19) 1(1482.52,505.19) 1(1484.19,-164.92) 1(1484.19,-123.92) 1(1485.09,-66.77) 1(1485.09,-25.77) 1(1485.09,-16.77) 1(1485.09,24.23) 1(1485.09,-116.78) 1(1485.09,-75.78) 1(1485.09,33.22) 1(1485.09,74.22) 1(1493.8,1166.5) 1(1493.8,1166.5) 1(1493.8,1189.5) 1(1493.8,1239.5) 1(1493.8,1262.5) 1(1493.8,1262.5) 1(1495.89,-931.23) 1(1495.89,-890.23) 1(1503.3,1209) 1(1503.3,1209) 1(1503.3,1250) 1(1503.3,1250) 1(1518.89,-931.23) 1(1518.89,-931.23) 1(1518.89,-890.23) 1(1518.89,-890.23) 1(1523.86,933.82) 1(1523.86,933.82) 1(1523.86,974.82) 1(1523.86,974.82) 1(1523.97,867.08) 1(1523.97,867.08) 1(1523.97,908.08) 1(1523.97,908.08) 1(1526.3,1209) 1(1526.3,1250) 1(1526.93,390.95) 1(1526.93,431.95) 1(1532.52,464.19) 1(1532.52,505.19) 1(1534.19,-164.92) 1(1534.19,-123.92) 1(1535.09,-66.77) 1(1535.09,-25.77) 1(1535.09,-16.77) 1(1535.09,24.23) 1(1535.09,-116.78) 1(1535.09,-75.78) 1(1535.09,33.22) 1(1535.09,74.22) 1(1546.86,933.82) 1(1546.86,974.82) 1(1546.97,867.08) 1(1546.97,908.08) 1(1549.93,390.95) 1(1549.93,390.95) 1(1549.93,431.95) 1(1549.93,431.95) 1(1555.52,464.19) 1(1555.52,464.19) 1(1555.52,505.19) 1(1555.52,505.19) 1(1557.19,-164.92) 1(1557.19,-164.92) 1(1557.19,-123.92) 1(1557.19,-123.92) 1(1558.09,-66.77) 1(1558.09,-66.77) 1(1558.09,-25.77) 1(1558.09,-25.77) 1(1558.09,-16.77) 1(1558.09,-16.77) 1(1558.09,24.23) 1(1558.09,24.23) 1(1558.09,-116.78) 1(1558.09,-116.78) 1(1558.09,-75.78) 1(1558.09,-75.78) 1(1558.09,33.22) 1(1558.09,33.22) 1(1558.09,74.22) 1(1558.09,74.22) 1(1561.77,-937) 1(1561.77,-937) 1(1561.77,-896) 1(1561.77,-896) 1(1568.24,-64.77) 1(1568.24,-64.77) 1(1568.24,-41.77) 1(1568.24,8.23) 1(1568.24,31.23) 1(1568.24,31.23) 1(1576.3,1209) 1(1576.3,1250) 1(1584.77,-937) 1(1584.77,-896) 1(1596.86,933.82) 1(1596.86,974.82) 1(1596.97,867.08) 1(1596.97,908.08) 1(1599.3,1209) 1(1599.3,1209) 1(1599.3,1250) 1(1599.3,1250) 1(1609.24,-64.77) 1(1609.24,-64.77) 1(1609.24,-41.77) 1(1609.24,8.23) 1(1609.24,31.23) 1(1609.24,31.23) 1(1618.71,750.61) 1(1618.71,750.61) 1(1618.71,845.88) 1(1618.71,845.88) 1(1619.86,933.82) 1(1619.86,933.82) 1(1619.86,974.82) 1(1619.86,974.82) 1(1619.97,867.08) 1(1619.97,867.08) 1(1619.97,908.08) 1(1619.97,908.08) 1(1629.52,-87.09) 1(1629.52,-87.09) 1(1629.52,8.18) 1(1629.52,8.18) 1(1634.77,-937) 1(1634.77,-896) 1(1654.14,750.61) 1(1654.14,845.88) 1(1657.77,-937) 1(1657.77,-937) 1(1657.77,-896) 1(1657.77,-896) 1(1664.96,-87.09) 1(1664.96,8.18) 1(1695.55,2779.94) 1(1695.55,2779.94) 1(1695.55,2820.94) 1(1695.55,2820.94) 1(1695.56,2838.95) 1(1695.56,2838.95) 1(1695.56,2879.95) 1(1695.56,2879.95) 1(1718.55,2779.94) 1(1718.55,2820.94) 1(1718.56,2838.95) 1(1718.56,2879.95) 1(1722.93,2992.94) 1(1722.93,2992.94) 1(1722.93,3033.94) 1(1722.93,3033.94) 1(1723.93,3046.94) 1(1723.93,3046.94) 1(1723.93,3087.94) 1(1723.93,3087.94) 1(1724.56,2674.95) 1(1724.56,2674.95) 1(1724.56,2715.95) 1(1724.56,2715.95) 1(1745.93,2992.94) 1(1745.93,3033.94) 1(1746.68,2728.82) 1(1746.68,2728.82) 1(1746.68,2751.82) 1(1746.68,2824.82) 1(1746.68,2835.07) 1(1746.68,2908.07) 1(1746.68,2931.07) 1(1746.68,2931.07) 1(1746.93,3046.94) 1(1746.93,3087.94) 1(1747.56,2674.95) 1(1747.56,2715.95) 1(1763.15,145.77) 1(1763.15,145.77) 1(1763.15,185.77) 1(1763.15,185.77) 1(1763.15,225.77) 1(1763.15,225.77) 1(1763.15,541.91) 1(1763.15,541.91) 1(1763.15,581.91) 1(1763.15,581.91) 1(1763.15,621.91) 1(1763.15,621.91) 1(1772.25,845.88) 1(1774.05,2941.82) 1(1774.05,2941.82) 1(1774.05,2964.82) 1(1774.05,3037.82) 1(1774.68,2622.83) 1(1774.68,2622.83) 1(1774.68,2645.83) 1(1774.68,2718.83) 1(1783.07,-87.09) 1(1783.07,8.18) 1(1787.68,2728.82) 1(1787.68,2728.82) 1(1787.68,2751.82) 1(1787.68,2824.82) 1(1787.68,2835.07) 1(1787.68,2908.07) 1(1787.68,2931.07) 1(1787.68,2931.07) 1(1791.55,2779.94) 1(1791.55,2820.94) 1(1791.56,2838.95) 1(1791.56,2879.95) 1(1796.93,3046.94) 1(1796.93,3087.94) 1(1797.15,145.77) 1(1797.15,225.77) 1(1797.15,541.91) 1(1797.15,621.91) 1(1807.41,-946.25) 1(1807.41,-946.25) 1(1807.41,-905.25) 1(1807.41,-905.25) 1(1807.68,759.61) 1(1807.68,845.88) 1(1807.68,845.88) 1(1815.05,2941.82) 1(1815.05,2941.82) 1(1815.05,2964.82) 1(1815.05,3037.82) 1(1815.68,2622.83) 1(1815.68,2622.83) 1(1815.68,2645.83) 1(1815.68,2718.83) 1(1818.5,-87.09) 1(1818.5,-87.09) 1(1818.5,8.18) 1(1818.5,8.18) 1(1818.93,2992.94) 1(1818.93,3033.94) 1(1819.93,3046.94) 1(1819.93,3046.94) 1(1819.93,3087.94) 1(1819.93,3087.94) 1(1820.56,2674.95) 1(1820.56,2715.95) 1(1830.41,-946.25) 1(1830.41,-905.25) 1(1877.15,145.77) 1(1877.15,225.77) 1(1877.15,541.91) 1(1877.15,621.91) 1(1880.41,-946.25) 1(1880.41,-905.25) 1(1903.41,-946.25) 1(1903.41,-946.25) 1(1903.41,-905.25) 1(1903.41,-905.25) 1(1909.15,541.91) 1(1909.15,541.91) 1(1909.15,581.91) 1(1909.15,581.91) 1(1909.15,621.91) 1(1909.15,621.91) 1(1911.15,145.77) 1(1911.15,145.77) 1(1911.15,145.91) 1(1911.15,145.91) 1(1911.15,185.77) 1(1911.15,185.77) 1(1911.15,185.91) 1(1911.15,185.91) 1(1911.15,225.77) 1(1911.15,225.77) 1(1911.15,225.91) 1(1911.15,225.91) 1(1911.15,541.91) 1(1911.15,541.91) 1(1911.15,581.91) 1(1911.15,581.91) 1(1911.15,621.91) 1(1911.15,621.91) 1(1943.15,541.91) 1(1943.15,621.91) 1(1945.15,145.91) 1(1945.15,225.91) 1(1955.06,2948.45) 1(1955.06,2948.45) 1(1955.06,2971.45) 1(1955.06,3021.45) 1(1955.06,3044.45) 1(1955.06,3044.45) 1(1958.06,2469.45) 1(1958.06,2469.45) 1(1958.06,2492.45) 1(1958.06,2542.45) 1(1958.06,2565.45) 1(1958.06,2565.45) 1(1960.8,-398.5) 1(1960.8,-398.5) 1(1960.8,-375.5) 1(1960.8,-325.5) 1(1960.8,-302.5) 1(1960.8,-302.5) 1(1981.06,2844.83) 1(1981.06,2844.83) 1(1981.06,2867.83) 1(1981.06,2917.83) 1(1981.06,2940.83) 1(1981.06,2940.83) 1(1996.06,2948.45) 1(1996.06,2948.45) 1(1996.06,2971.45) 1(1996.06,3021.45) 1(1996.06,3044.45) 1(1996.06,3044.45) 1(1999.06,2469.45) 1(1999.06,2469.45) 1(1999.06,2492.45) 1(1999.06,2542.45) 1(1999.06,2565.45) 1(1999.06,2565.45) 1(2001.8,-398.5) 1(2001.8,-398.5) 1(2001.8,-375.5) 1(2001.8,-325.5) 1(2001.8,-302.5) 1(2001.8,-302.5) 1(2004.55,758.91) 1(2004.55,758.91) 1(2004.55,947.88) 1(2004.55,947.88) 1(2004.55,794.34) 1(2004.55,912.45) 1(2010.66,-93.73) 1(2010.66,-93.73) 1(2010.66,1.55) 1(2010.66,1.55) 1(2022.06,2844.83) 1(2022.06,2844.83) 1(2022.06,2867.83) 1(2022.06,2917.83) 1(2022.06,2940.83) 1(2022.06,2940.83) 1(2023.15,541.91) 1(2023.15,621.91) 1(2024.8,-398.5) 1(2024.8,-398.5) 1(2024.8,-375.5) 1(2024.8,-325.5) 1(2024.8,-302.5) 1(2024.8,-302.5) 1(2025.15,145.91) 1(2025.15,225.91) 1(2046.09,-93.73) 1(2046.09,1.55) 1(2057.15,541.91) 1(2057.15,541.91) 1(2057.15,581.91) 1(2057.15,581.91) 1(2057.15,621.91) 1(2057.15,621.91) 1(2059.15,145.91) 1(2059.15,145.91) 1(2059.15,185.91) 1(2059.15,185.91) 1(2059.15,225.91) 1(2059.15,225.91) 1(2065.8,-398.5) 1(2065.8,-398.5) 1(2065.8,-375.5) 1(2065.8,-325.5) 1(2065.8,-302.5) 1(2065.8,-302.5) 1(2072.93,2891.94) 1(2072.93,2891.94) 1(2072.93,2901.94) 1(2072.93,2901.94) 1(2072.93,2942.94) 1(2072.93,2942.94) 1(2072.93,2850.94) 1(2072.93,2850.94) 1(2092.93,-1615.05) 1(2092.93,-1615.05) 1(2092.93,-1606.06) 1(2092.93,-1467.05) 1(2092.93,-1458.05) 1(2092.93,-1458.05) 1(2093.93,2527) 1(2093.93,2527) 1(2093.93,2568) 1(2093.93,2568) 1(2093.93,2475.94) 1(2093.93,2475.94) 1(2093.93,2516.94) 1(2093.93,2516.94) 1(2093.93,2584.98) 1(2093.93,2584.98) 1(2093.93,2625.98) 1(2093.93,2625.98) 1(2094.56,2634.95) 1(2094.56,2634.95) 1(2094.56,2675.95) 1(2094.56,2675.95) 1(2095.56,2684.95) 1(2095.56,2684.95) 1(2095.56,2725.95) 1(2095.56,2725.95) 1(2095.93,2850.94) 1(2095.93,2891.94) 1(2095.93,2901.94) 1(2095.93,2942.94) 1(2099.82,912.45) 1(2099.82,758.91) 1(2099.82,758.91) 1(2099.82,947.88) 1(2099.82,947.88) 1(2099.82,767.85) 1(2116.93,2527) 1(2116.93,2568) 1(2116.93,2584.98) 1(2116.93,2625.98) 1(2116.93,2475.94) 1(2116.93,2516.94) 1(2117.56,2634.95) 1(2117.56,2675.95) 1(2118.56,2684.95) 1(2118.56,2725.95) 1(2145.93,2891.94) 1(2145.93,2901.94) 1(2145.93,2942.94) 1(2145.93,2850.94) 1(2164.2,-93.73) 1(2164.2,1.55) 1(2166.93,2527) 1(2166.93,2568) 1(2166.93,2475.94) 1(2166.93,2516.94) 1(2166.93,2584.98) 1(2166.93,2625.98) 1(2167.56,2634.95) 1(2167.56,2675.95) 1(2168.56,2684.95) 1(2168.56,2725.95) 1(2168.93,2850.94) 1(2168.93,2850.94) 1(2168.93,2891.94) 1(2168.93,2891.94) 1(2168.93,2901.94) 1(2168.93,2901.94) 1(2168.93,2942.94) 1(2168.93,2942.94) 1(2189.93,2527) 1(2189.93,2527) 1(2189.93,2568) 1(2189.93,2568) 1(2189.93,2584.98) 1(2189.93,2584.98) 1(2189.93,2625.98) 1(2189.93,2625.98) 1(2189.93,2475.94) 1(2189.93,2475.94) 1(2189.93,2516.94) 1(2189.93,2516.94) 1(2190.56,2634.95) 1(2190.56,2634.95) 1(2190.56,2675.95) 1(2190.56,2675.95) 1(2191.56,2684.95) 1(2191.56,2684.95) 1(2191.56,2725.95) 1(2191.56,2725.95) 1(2199.63,-93.73) 1(2199.63,-93.73) 1(2199.63,1.55) 1(2199.63,1.55) 1(2281.3,-1390.5) 1(2281.3,-1390.5) 1(2281.3,-1356.5) 1(2281.3,-1276.5) 1(2281.3,-1242.5) 1(2281.3,-1242.5) 1(2321.3,-1390.5) 1(2321.3,-1390.5) 1(2321.3,-1242.5) 1(2321.3,-1242.5) 1(2359.93,-1615.05) 1(2359.93,-1458.05) 1(2361.3,-1390.5) 1(2361.3,-1390.5) 1(2361.3,-1356.5) 1(2361.3,-1276.5) 1(2361.3,-1242.5) 1(2361.3,-1242.5) 1(2371.3,-1390.5) 1(2371.3,-1390.5) 1(2371.3,-1356.5) 1(2371.3,-1276.5) 1(2371.3,-1242.5) 1(2371.3,-1242.5) 1(2411.3,-1390.5) 1(2411.3,-1390.5) 1(2411.3,-1242.5) 1(2411.3,-1242.5) 1(2426.84,2418.71) 1(2426.84,2418.71) 1(2426.84,2456.31) 1(2426.84,2516.31) 1(2426.84,2553.91) 1(2426.84,2553.91) 1(2435.3,2367.9) 1(2435.3,2367.9) 1(2435.3,2408.9) 1(2435.3,2408.9) 1(2451.3,-1390.5) 1(2451.3,-1390.5) 1(2451.3,-1356.5) 1(2451.3,-1276.5) 1(2451.3,-1242.5) 1(2451.3,-1242.5) 1(2451.31,1705.87) 1(2451.31,1705.87) 1(2451.31,1760.34) 1(2451.31,1760.34) 1(2458.3,2367.9) 1(2458.3,2408.9) 1(2477.3,1705.87) 1(2477.3,1760.34) 1(2488.3,2166) 1(2488.3,2166) 1(2488.3,2207) 1(2488.3,2207) 1(2498.8,1061.5) 1(2498.8,1061.5) 1(2498.8,1084.5) 1(2498.8,1134.5) 1(2498.8,1157.5) 1(2498.8,1157.5) 1(2502.34,2418.71) 1(2502.34,2418.71) 1(2502.34,2553.91) 1(2502.34,2553.91) 1(2503.04,2419.4) 1(2503.04,2419.4) 1(2503.04,2456.31) 1(2503.04,2516.31) 1(2503.04,2553.21) 1(2503.04,2553.21) 1(2507.8,793.88) 1(2507.8,793.88) 1(2507.8,816.88) 1(2507.8,866.88) 1(2507.8,889.88) 1(2507.8,889.88) 1(2508.3,2367.9) 1(2508.3,2408.9) 1(2511.3,2166) 1(2511.3,2207) 1(2521.3,2417.5) 1(2521.3,2417.5) 1(2521.3,2451.5) 1(2521.3,2531.5) 1(2521.3,2565.5) 1(2521.3,2565.5) 1(2523.35,1443.52) 1(2523.35,1443.52) 1(2523.35,1469.5) 1(2523.35,1537.5) 1(2523.35,1563.49) 1(2523.35,1563.49) 1(2531.3,2367.9) 1(2531.3,2367.9) 1(2531.3,2408.9) 1(2531.3,2408.9) 1(2539.8,1061.5) 1(2539.8,1061.5) 1(2539.8,1084.5) 1(2539.8,1134.5) 1(2539.8,1157.5) 1(2539.8,1157.5) 1(2545.3,1705.87) 1(2545.3,1760.34) 1(2548.8,793.88) 1(2548.8,793.88) 1(2548.8,816.88) 1(2548.8,866.88) 1(2548.8,889.88) 1(2548.8,889.88) 1(2561.3,2166) 1(2561.3,2207) 1(2561.3,2417.5) 1(2561.3,2417.5) 1(2561.3,2565.5) 1(2561.3,2565.5) 1(2571.28,1705.87) 1(2571.28,1705.87) 1(2571.28,1760.34) 1(2571.28,1760.34) 1(2577.82,1443.52) 1(2577.82,1443.52) 1(2577.82,1469.5) 1(2577.82,1537.5) 1(2577.82,1563.49) 1(2577.82,1563.49) 1(2584.3,2166) 1(2584.3,2166) 1(2584.3,2207) 1(2584.3,2207) 1(2601.3,2417.5) 1(2601.3,2417.5) 1(2601.3,2451.5) 1(2601.3,2531.5) 1(2601.3,2565.5) 1(2601.3,2565.5) 1(2604.12,-940.34) 1(2604.12,-940.34) 1(2604.12,-917.34) 1(2604.12,-867.34) 1(2604.12,-844.34) 1(2604.12,-844.34) 1(2614.3,2599.01) 1(2614.3,2599.01) 1(2614.3,2640.01) 1(2614.3,2640.01) 1(2619.3,2671.01) 1(2619.3,2671.01) 1(2619.3,2712.01) 1(2619.3,2712.01) 1(2637.3,2599.01) 1(2637.3,2640.01) 1(2642.3,2671.01) 1(2642.3,2712.01) 1(2642.64,1472.43) 1(2642.64,1472.43) 1(2642.64,1496.05) 1(2642.64,1771.64) 1(2642.64,1795.26) 1(2642.64,1795.26) 1(2642.64,2147.43) 1(2642.64,2147.43) 1(2642.64,2171.05) 1(2642.64,2446.64) 1(2642.64,2470.26) 1(2642.64,2470.26) 1(2645.12,-940.34) 1(2645.12,-940.34) 1(2645.12,-917.34) 1(2645.12,-867.34) 1(2645.12,-844.34) 1(2645.12,-844.34) 1(2675.8,-941.5) 1(2675.8,-941.5) 1(2675.8,-918.5) 1(2675.8,-868.5) 1(2675.8,-845.5) 1(2675.8,-845.5) 1(2687.3,2599.01) 1(2687.3,2640.01) 1(2692.3,2671.01) 1(2692.3,2712.01) 1(2705.64,1472.43) 1(2705.64,1795.26) 1(2705.64,2147.43) 1(2705.64,2470.26) 1(2710.3,2599.01) 1(2710.3,2599.01) 1(2710.3,2640.01) 1(2710.3,2640.01) 1(2715.3,2671.01) 1(2715.3,2671.01) 1(2715.3,2712.01) 1(2715.3,2712.01) 1(2716.8,-941.5) 1(2716.8,-941.5) 1(2716.8,-918.5) 1(2716.8,-868.5) 1(2716.8,-845.5) 1(2716.8,-845.5)
  round 78.74 on Mech16: 1(147.93,-1533.55) 1(188.93,3200.45) 1(2623.93,3271.45)
  round 170 on Mech16: 1(184.83,500.98) 1(187.93,3524.45) 1(2416.93,3544.45) 1(2424.83,500.98)
  round 50 on Mech16: 1(203.18,-459.76) 1(203.18,332.76) 1(673.34,918.78) 1(673.34,1711.29)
